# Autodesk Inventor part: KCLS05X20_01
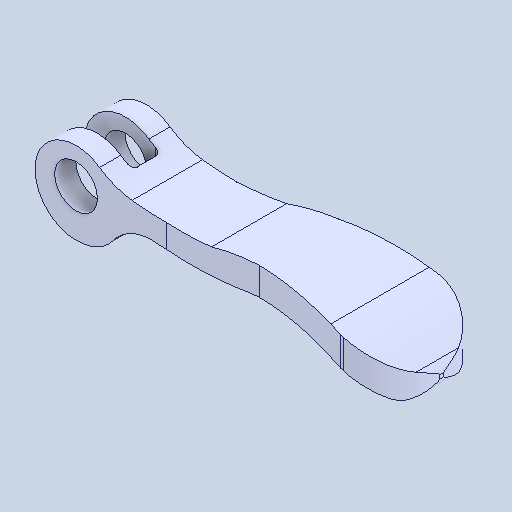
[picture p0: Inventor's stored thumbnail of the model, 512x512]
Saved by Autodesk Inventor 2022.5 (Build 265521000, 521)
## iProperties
Created: 2024-08
Part Number: KCLS05X20_01
Material: 一般
Document SubType Name: Modeling
Designer: ImaoCorp
Density: 1 g/cm^3
Appearance: 既定
Author: ImaoCorp
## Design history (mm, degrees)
feature "KCLS05X20_01"
node "ソリッド1"
